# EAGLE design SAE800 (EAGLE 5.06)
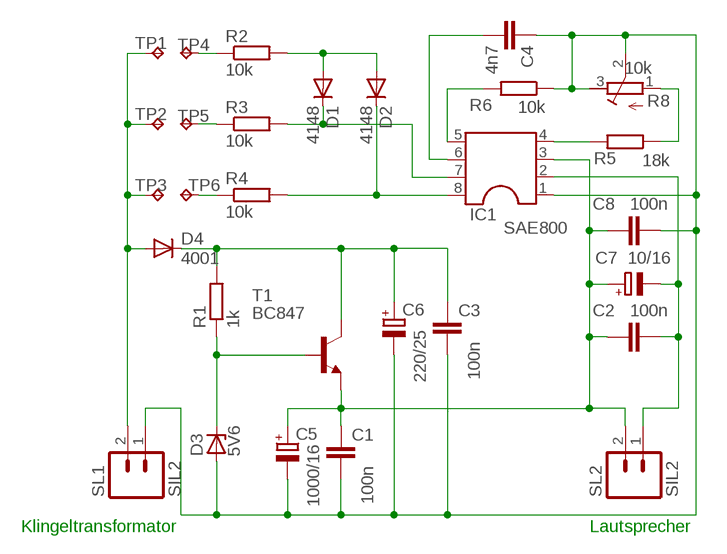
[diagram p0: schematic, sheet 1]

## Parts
C1  100n  C-EUC1206K  [C1206K]
C2  100n  C-EUC1206K  [C1206K]
C3  100n  C-EUC1206K  [C1206K]
C4  4n7  C-EUC1206K  [C1206K]
C5  1000/16  CPOL-EUE5-10.5  [E5-10,5]
C6  220/25  CPOL-EUE5-8.5  [E5-8,5]
C7  10/16  CPOL-EUSMCC  [SMC_C]
C8  100n  C-EUC1206K  [C1206K]
D1  4148  CGRM4002-G  [SOD-123_MINI-SMA]
D2  4148  CGRM4002-G  [SOD-123_MINI-SMA]
D3  5V6  ZENER-DIODESMB  [SMB]
D4  4001  CGRM4007-G  [SOD-123_MINI-SMA]
IC1  SAE800  DIL8S  [SOCKET-08]
R1  1k  R-EU_0207/7  [0207/7]
R2  10k  R-EU_0207/7  [0207/7]
R3  10k  R-EU_0207/7  [0207/7]
R4  10k  R-EU_0207/7  [0207/7]
R5  18k  R-EU_0207/7  [0207/7]
R6  10k  R-EU_0207/7  [0207/7]
R8  10k  R-TRIMM3224J  [RTRIM3224J]
SL1  SIL2  M02  [02P]
SL2  SIL2  M02  [02P]
T1  BC847  -NPN-TO92-ECB  [TO92-ECB]
TP1  TPTP19R  [TP19R]
TP2  TPTP19R  [TP19R]
TP3  TPTP19R  [TP19R]
TP4  TPTP19R  [TP19R]
TP5  TPTP19R  [TP19R]
TP6  TPTP19R  [TP19R]

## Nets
N$1: D4.A SL1.2 TP1.TP TP2.TP TP3.TP
N$2: C3.1 C6.+ D4.C R1.2 T1.C
N$3: D3.C R1.1 T1.B
N$4: C4.2 IC1.6
N$5: IC1.4 R5.2
N$6: C1.2 C3.2 C4.1 C5.- C6.- C8.2 D3.A IC1.1 R6.1 R8.2(S) R8.3(A) SL1.1
N$7: R2.1 TP4.TP
N$8: R3.1 TP5.TP
N$9: R4.1 TP6.TP
N$10: D1.A D2.A R2.2
N$11: C2.2 C7.- IC1.2 SL2.1
N$12: IC1.5 R6.2
N$13: D1.C IC1.7 R3.2
N$14: D2.C IC1.8 R4.2
N$15: R5.1 R8.1(E)
N$19: C1.1 C2.1 C5.+ C7.+ C8.1 IC1.3 SL2.2 T1.E

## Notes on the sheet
- Klingeltransformator | Lautsprecher

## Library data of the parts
C1-C4 C8 = resistor:C-EU: CAPACITOR, European symbol
C5-C7 = resistor:CPOL-EU: POLARIZED CAPACITOR, European symbol
D1 D2 D4 = diode:CGRM400*-G: Molded plasitc,JEDEC SOD-123/Mini SMA
D3 = diode:ZENER-DIODE: Z-Diode
IC1 = ic-package:DIL8: Dual In Line / Socket
R1-R6 = resistor:R-EU_: RESISTOR, European symbol
R8 = resistor:R-TRIMM: Trimm resistor
SL1 SL2 = con-amp-quick:M02: AMP QUICK CONNECTOR
T1 = transistor:*-NPN-: NPN Transistror BF959 corrected 2008.03.06
TP1-TP6 = testpad:TP: Test pad

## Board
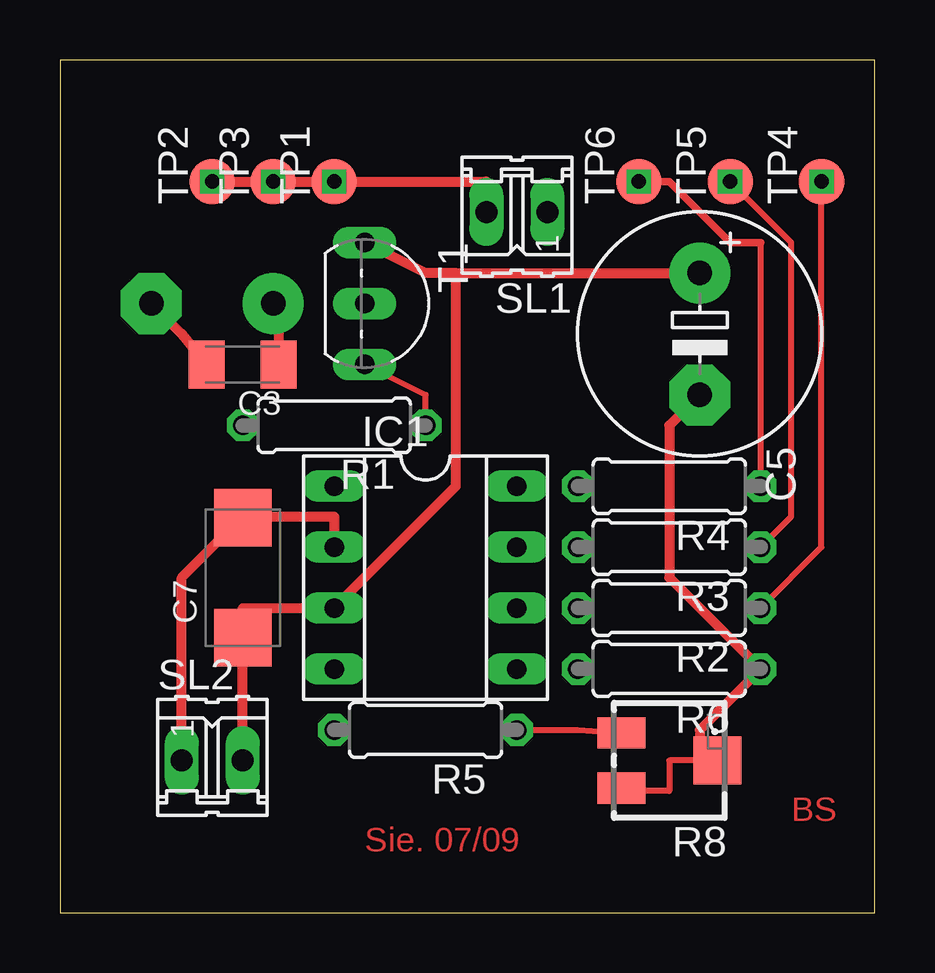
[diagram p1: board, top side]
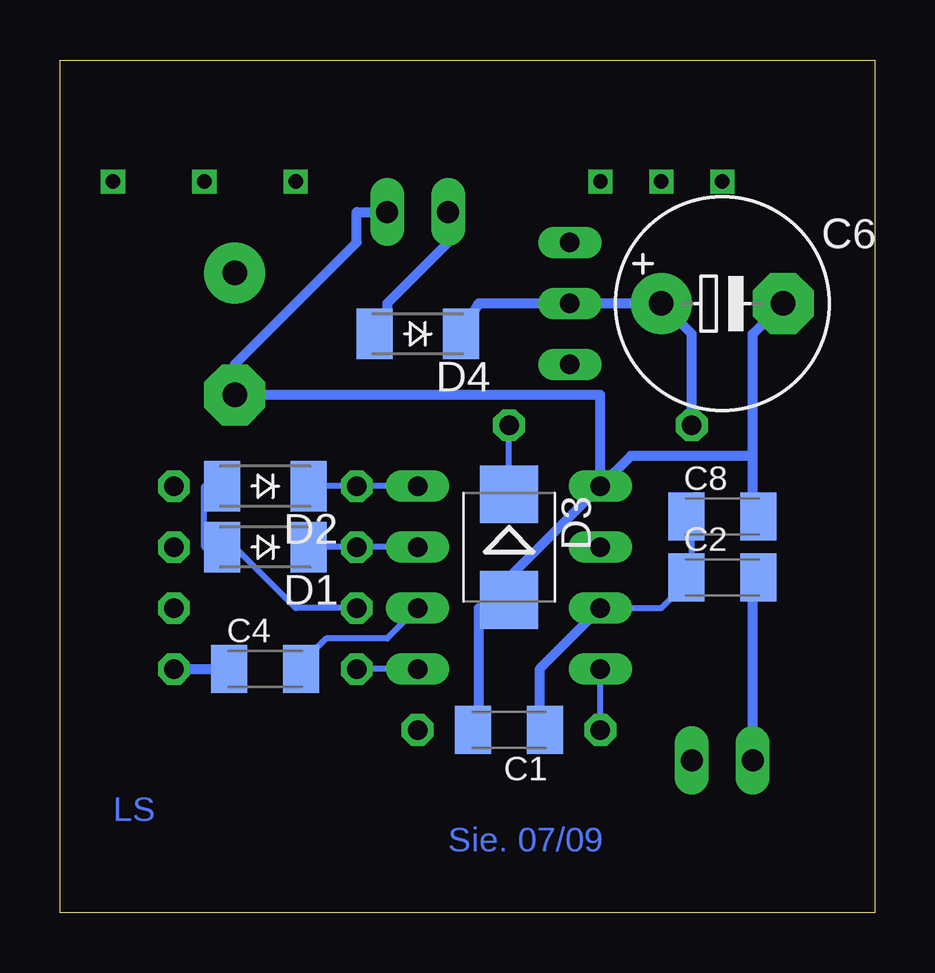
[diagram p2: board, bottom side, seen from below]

Size 33.96 x 35.55 mm. Coordinates in mm from the lower left corner, seen from the top.
Outline: 0,0 33.96,0 33.96,35.55 0,35.55 0,0
Copper layers (1*16): Top 0.035mm / dielectric 1.5mm / Bottom 0.035mm
Design rules "default": minimum track width 10mil, minimum drill 24mil, track to track 8mil, track to pad 8mil, pad to pad 8mil, via to via 8mil, smd to smd 8mil, copper to edge 40mil, drill to drill 8mil, minimum pad ring 10mil, minimum via ring 8mil, stop-mask expansion 4mil, vias tented up to drill 0mil, thermal gap 10mil

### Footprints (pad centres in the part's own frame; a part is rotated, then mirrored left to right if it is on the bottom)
C1206K = smd 1.5 x 2: 1 -1.5,0; 2 1.5,0
E5-10,5 = drill 1.016 pad 2.54 round: + -2.54,0 | drill 1.016 pad 2.54 octagon: - 2.54,0
E5-8,5 = drill 1.016 pad 2.54 round: + -2.54,0 | drill 1.016 pad 2.54 octagon: - 2.54,0
SMC_C = smd 2.4 x 2.4: + -2.5,0; - 2.5,0
SOD-123_MINI-SMA = smd 1.5 x 2.1: A 1.8,0; C -1.8,0
SMB = smd 2.4 x 2.4: A 2.2,0; C -2.2,0
SOCKET-08 = drill 0.813 long: 1 -3.81,-3.81; 2 -1.27,-3.81; 3 1.27,-3.81; 4 3.81,-3.81; 5 3.81,3.81; 6 1.27,3.81; 7 -1.27,3.81; 8 -3.81,3.81
0207/7 = drill 0.813 octagon: 1 -3.81,0; 2 3.81,0
RTRIM3224J = smd 1.3 x 2: 1 -1.15,-2; 3 1.15,-2 | smd 2 x 2: 2 0,2
02P = drill 0.914 long: 1 -1.27,0; 2 1.27,0
TO92-ECB = drill 0.813 long: B 2.54,0; C 0,0; E -2.54,0
TP19R = smd 1.9 x 1.9: TP 0,0

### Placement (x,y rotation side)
C1  15.24,7.62 180 bottom
C2  6.35,13.97 0 bottom
C3  7.62,22.86 180 top
C4  25.4,10.16 0 bottom
C5  26.67,24.13 270 top
C6  6.35,25.4 0 bottom
C7  7.62,13.97 90 top
C8  6.35,16.51 0 bottom
D1  25.4,15.24 180 bottom
D2  25.4,17.78 180 bottom
D3  15.24,15.24 270 bottom
D4  19.05,24.13 180 bottom
IC1  15.24,13.97 270 top
R1  11.43,20.32 180 top
R2  25.4,12.7 180 top
R3  25.4,15.24 180 top
R4  25.4,17.78 180 top
R5  15.24,7.62 180 top
R6  25.4,10.16 180 top
R8  25.4,6.35 270 top
SL1  19.05,29.21 180 top
SL2  6.35,6.35 0 top
T1  12.7,25.4 270 top
TP1  11.43,30.48 90 top
TP2  6.35,30.48 90 top
TP3  8.89,30.48 90 top
TP4  31.75,30.48 90 top
TP5  27.94,30.48 90 top
TP6  24.13,30.48 90 top

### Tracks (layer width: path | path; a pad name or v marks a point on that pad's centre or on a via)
N$1  (via drill 0.6)
  Top 0.406: TP2.TP TP3.TP TP1.TP 17.78,30.48 SL1.2
  Bottom 0.406: SL1.2 17.78,27.94 20.32,25.4 20.32,24.66 D4.A
  other vias: 6.35,30.48 8.89,30.48 11.43,30.48
N$2
  Top 0.406: C3.1 9.12,25.17 C6.+
  Bottom 0.406: D4.C 16.51,25.4 T1.C C6.+ 7.62,24.13 R1.2
N$3
  Top 0.254: T1.B 15.24,21.59 R1.1
  Bottom 0.254: D3.C R1.1
N$4
  Bottom 0.254: IC1.6 20.32,11.43 22.86,11.43 24.13,10.16 C4.2
N$5
  Bottom 0.254: R5.2 IC1.4
N$6
  Top 0.254: R8.3 22.86,5.08 25.4,5.08 25.4,6.35 R8.2 26.67,6.35
  Top 0.406: 26.67,6.35 26.67,7.62 R6.1 25.4,13.97 25.4,20.32 C5.- | C3.2 5.08,24.13 C6.-
  Bottom 0.254: C4.1 26.67,10.16 | C8.2 5.08,16.51 | 15.24,13.97 D3.A 15.24,12.7 16.51,12.7 | 16.51,7.62 C1.2
  Bottom 0.406: R6.1 C4.1 | SL1.1 21.59,29.21 21.59,27.94 26.67,22.86 C5.- 11.43,21.59 IC1.1 | 5.08,16.51 5.08,19.05 | 5.08,19.05 10.16,19.05 IC1.1 | IC1.1 15.24,13.97 | 16.51,12.7 16.51,7.62 | 5.08,19.05 5.08,24.13 C6.-
N$7  (via drill 0.6)
  Top 0.254: TP4.TP 31.75,15.24 R2.1
  other vias: 31.75,30.48
N$8  (via drill 0.6)
  Top 0.254: TP5.TP 30.48,27.94 30.48,16.51 R3.1
  other vias: 27.94,30.48
N$9  (via drill 0.6)
  Top 0.254: R4.1 29.21,27.94
  Top 0.305: 29.21,27.94 27.94,27.94 25.4,30.48 TP6.TP
  other vias: 24.13,30.48
N$10
  Bottom 0.254: D2.A 27.94,17.78 27.94,15.24 D1.A 26.67,15.24 24.13,12.7 R2.2
N$11
  Top 0.254: 7.62,16.51 C7.-
  Top 0.406: IC1.2 11.43,16.51 7.62,16.51 5.08,13.97 SL2.1
  Bottom 0.254: 5.08,13.97 C2.2
  Bottom 0.406: SL2.1 5.08,13.97
N$12
  Bottom 0.254: IC1.5 R6.2
N$13
  Bottom 0.254: D1.C R3.2 IC1.7
N$14
  Bottom 0.254: IC1.8 R4.2 D2.C
N$15
  Top 0.254: R5.1 21.59,7.62 R8.1
N$19
  Top 0.406: SL2.2 C7.+ 7.62,12.7 IC1.3 16.51,17.78 16.51,26.67 | 16.51,26.67 C5.+ | 16.51,26.67 15.24,26.67 T1.E
  Bottom 0.254: 7.62,13.97 7.62,16.51 C8.1 | 7.62,13.97 8.89,12.7 IC1.3 | 7.62,13.97 C2.1 | 13.97,7.62 C1.1
  Bottom 0.406: 13.97,7.62 13.97,10.16 IC1.3

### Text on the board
Top: BS | Sie. 07/09
Bottom: LS | Sie. 07/09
